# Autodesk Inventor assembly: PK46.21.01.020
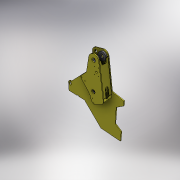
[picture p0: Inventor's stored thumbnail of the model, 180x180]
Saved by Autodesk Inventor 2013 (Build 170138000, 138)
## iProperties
Created: 2005-04
Part Number: PK46.21.01.020
Document SubType Name: Assembly
Designer: salex
Manufacturer: Standard
Standards Organization: Custom
Author: salex
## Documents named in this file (9)
- C:\Product Design Suite 2013 Test Drive\Dynamic Simulation\Workspace\Assy, Chassis, Front\PK46.21.01.020.iam
- C:\Product Design Suite 2013 Test Drive\Dynamic Simulation\Workspace\Assy, Chassis, Front\PK46.21.01.002.ipt
- C:\Product Design Suite 2013 Test Drive\Dynamic Simulation\Workspace\Assy, Chassis, Front\PK46.21.01.033.ipt
- C:\Product Design Suite 2013 Test Drive\Dynamic Simulation\Workspace\Assy, Chassis, Front\PK46.21.01.003.ipt
- C:\Product Design Suite 2013 Test Drive\Dynamic Simulation\Workspace\Assy, Chassis, Front\PK46.21.01.004.ipt
- C:\Product Design Suite 2013 Test Drive\Dynamic Simulation\Workspace\Assy, Chassis, Front\PK46.21.01.005.ipt
- C:\Product Design Suite 2013 Test Drive\Dynamic Simulation\Workspace\Assy, Chassis, Front\PK46.80.00.015.ipt
- C:\Product Design Suite 2013 Test Drive\Dynamic Simulation\Workspace\Assy, Chassis, Front\PK46.21.01.034.ipt
- C:\Product Design Suite 2013 Test Drive\Dynamic Simulation\Workspace\Assy, Chassis, Front\PK46.21.01.001.ipt
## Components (10 placed, 8 different names)
1. PK46.21.01.002:1 — Совмещение:1, Вставка:2, Совмещение:6, Вставка:4, Mate:13, Mate:14, Совмещение:16, Угол:1, Совмещение:15, Insert:7
2. PK46.21.01.003:1 — Insert:6
3. PK46.21.01.003:2 — Вставка:4
4. PK46.21.01.004:1 — Совмещение:6, Совмещение:10
5. PK46.21.01.005:1 — Совмещение:1, Совмещение:10, Flush:3, Mate:12
6. PK46.80.00.015:1 — Вставка:2, Заподлицо:2
7. PK46.80.00.015:2 — Insert:5
8. PK46.21.01.034:1 — Insert:7
9. PK46.21.01.001:1 — Insert:5, Insert:6, Flush:3, Mate:12, Mate:13, Mate:14
10. PK46.21.01.033:1 — Совмещение:16, Угол:1, Совмещение:15
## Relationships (16: Mate 8, Insert 5, Flush 2, Angle 1)
- Совмещение:1 [Mate]: PK46.21.01.002:1 ↔ PK46.21.01.005:1
- Вставка:2 [Insert]: PK46.21.01.002:1 ↔ PK46.80.00.015:1
- Совмещение:6 [Mate]: PK46.21.01.002:1 ↔ PK46.21.01.004:1
- Вставка:4 [Insert]: PK46.21.01.002:1 ↔ PK46.21.01.003:2
- Заподлицо:2 [Flush]: PK46.80.00.015:1
- Совмещение:10 [Mate]: PK46.21.01.004:1 ↔ PK46.21.01.005:1
- Insert:5: PK46.80.00.015:2 ↔ PK46.21.01.001:1
- Insert:6: PK46.21.01.003:1 ↔ PK46.21.01.001:1
- Flush:3: PK46.21.01.005:1 ↔ PK46.21.01.001:1
- Mate:12: PK46.21.01.005:1 ↔ PK46.21.01.001:1
- Mate:13: PK46.21.01.002:1 ↔ PK46.21.01.001:1
- Mate:14: PK46.21.01.002:1 ↔ PK46.21.01.001:1
- Insert:7: PK46.21.01.002:1 ↔ PK46.21.01.034:1
- Совмещение:16 [Mate]: PK46.21.01.002:1 ↔ PK46.21.01.033:1
- Угол:1 [Angle]: PK46.21.01.002:1 ↔ PK46.21.01.033:1
- Совмещение:15 [Mate]: PK46.21.01.002:1 ↔ PK46.21.01.033:1
